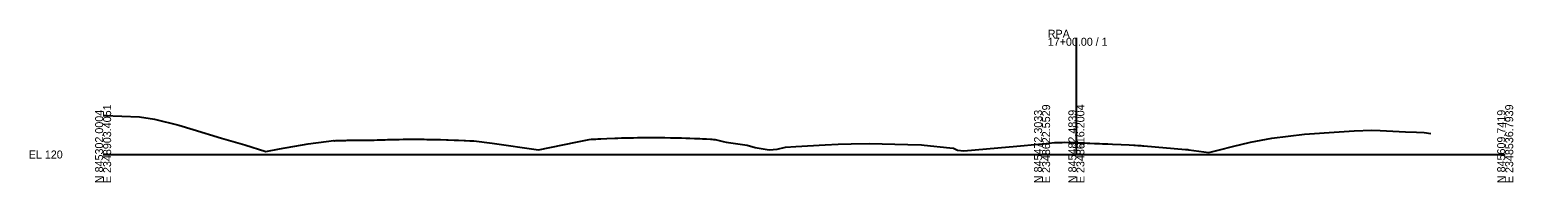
# Model space of a CAD drawing. Extents: x -76 to 2348158, y -10 to 845166.
# Drawn here: x 1224 to 1743, y 6490 to 6544 of the extents above; entities that cross this region are included whole.
import ezdxf

# ---------------------------------------------------------------- set-up
doc = ezdxf.new("R2010")
doc.units = 0
for name, color, linetype in [('Default', 7, 'Continuous'), ('Exist Cross Section Cell', 7, 'Continuous'), ('Exist XS Center Line Elevation Label', 7, 'Continuous'), ('Exist XS Ground Line', 7, 'Continuous')]:
    doc.layers.add(name, color=color, linetype=linetype)

msp = doc.modelspace()

# ---------------------------------------------------------------- linework, layer by layer
at = {"layer": 'Exist Cross Section Cell'}
for p, q in [((1590.45, 6500), (1590.45, 6540.75)), ((1250, 6500), (1578.45, 6500)), ((1578.45, 6500), (1590.45, 6500)), ((1590.45, 6500), (1740.45, 6500))]:
    msp.add_line(p, q, dxfattribs=at)
at = {"layer": 'Exist XS Ground Line'}
msp.add_lwpolyline([(1250, 6513.58), (1250.39, 6513.58), (1262.72, 6513.16), (1268.03, 6512.29), (1276.44, 6510.25), (1281.47, 6508.78), (1291.42, 6505.7), (1299.52, 6503.41), (1306.91, 6501.04), (1311.74, 6501.96), (1321.68, 6503.77), (1327.97, 6504.52), (1330.69, 6504.87), (1330.99, 6504.79), (1331.43, 6504.84), (1332.53, 6504.89), (1333.56, 6504.92), (1334.15, 6504.93), (1334.89, 6504.94), (1335.42, 6504.95), (1336.83, 6504.98), (1338.65, 6505), (1339.13, 6505), (1340.47, 6505.01), (1341.28, 6505.02), (1344.19, 6505.05), (1344.83, 6505.06), (1345.84, 6505.08), (1347.12, 6505.12), (1348.68, 6505.16), (1349.5, 6505.18), (1350.01, 6505.2), (1351.36, 6505.24), (1352.95, 6505.27), (1353.6, 6505.28), (1354.99, 6505.3), (1355.85, 6505.32), (1356.7, 6505.32), (1357.63, 6505.34), (1358.42, 6505.34), (1358.75, 6505.34), (1360.42, 6505.32), (1361.67, 6505.31), (1362.25, 6505.3), (1363.23, 6505.29), (1364.11, 6505.28), (1364.63, 6505.26), (1366.87, 6505.21), (1367.98, 6505.18), (1370.07, 6505.13), (1370.73, 6505.1), (1372.8, 6505.04), (1373.38, 6505.02), (1374.28, 6504.99), (1376.32, 6504.92), (1376.8, 6504.9), (1378.3, 6504.79), (1379.64, 6504.77), (1379.67, 6504.8), (1386.13, 6503.92), (1402.32, 6501.66), (1415.32, 6504.29), (1420.06, 6505.27), (1420.69, 6505.3), (1421.49, 6505.35), (1422.32, 6505.39), (1423.09, 6505.43), (1424.14, 6505.48), (1426.23, 6505.57), (1428.97, 6505.68), (1430.08, 6505.73), (1431.28, 6505.77), (1431.88, 6505.78), (1433.26, 6505.81), (1435.06, 6505.86), (1435.5, 6505.87), (1436.91, 6505.9), (1437.74, 6505.91), (1440.3, 6505.95), (1440.67, 6505.96), (1441.96, 6505.97), (1443.04, 6505.95), (1443.53, 6505.95), (1444.15, 6505.94), (1445.13, 6505.92), (1445.99, 6505.9), (1446.53, 6505.89), (1448.48, 6505.85), (1449.36, 6505.83), (1449.96, 6505.82), (1452.31, 6505.77), (1453.86, 6505.74), (1454.43, 6505.72), (1455.19, 6505.68), (1456.89, 6505.62), (1458.15, 6505.56), (1458.71, 6505.54), (1459.67, 6505.49), (1460.53, 6505.45), (1461.04, 6505.43), (1462.44, 6505.35), (1462.97, 6505.32), (1463.48, 6505.26), (1464.08, 6505.28), (1466.86, 6504.54), (1467.97, 6504.28), (1475.25, 6503.26), (1478.14, 6502.49), (1483.01, 6501.6), (1485.77, 6501.88), (1488.64, 6502.59), (1492.35, 6502.78), (1502.56, 6503.39), (1507.07, 6503.63), (1511.71, 6503.69), (1517.92, 6503.81), (1531.51, 6503.5), (1536.32, 6503.41), (1537.21, 6503.3), (1546.23, 6502.29), (1547.47, 6502.16), (1548.84, 6501.57), (1551.11, 6501.23), (1566.99, 6502.67), (1568.37, 6502.78), (1578.45, 6503.72), (1578.88, 6503.76), (1582.84, 6504.15), (1583.57, 6504.17), (1584.3, 6504.18), (1585.43, 6504.22), (1586.13, 6504.26), (1587.62, 6504.23), (1588.33, 6504.21), (1590.07, 6504.15), (1590.45, 6504.13), (1591.27, 6504.1), (1592, 6504.08), (1593.34, 6504.03), (1594.23, 6503.99), (1595.21, 6503.95), (1596.75, 6503.88), (1597.21, 6503.86), (1598.56, 6503.79), (1599.56, 6503.75), (1600.1, 6503.73), (1601.41, 6503.67), (1603.05, 6503.6), (1606.08, 6503.47), (1608.95, 6503.33), (1610.52, 6503.26), (1610.97, 6503.24), (1611.89, 6503.19), (1612.68, 6503.14), (1613.05, 6503.11), (1613.59, 6503.08), (1614.06, 6503.06), (1628.63, 6501.77), (1629.41, 6501.71), (1629.78, 6501.66), (1636.74, 6500.74), (1640.5, 6501.58), (1645.09, 6502.74), (1651.37, 6504.3), (1658.76, 6505.66), (1670.24, 6507.05), (1682.36, 6507.94), (1687.66, 6508.28), (1693.83, 6508.49), (1696.67, 6508.41), (1705.62, 6507.9), (1709.44, 6507.78), (1712.15, 6507.7), (1714.4, 6507.35)], dxfattribs=at)

# ---------------------------------------------------------------- texts
at = {"layer": 'Default'}
msp.add_text('-', height=0.0001, dxfattribs=at).set_placement((1250, 6500))
at = {"layer": 'Exist Cross Section Cell'}
for s, p in [('17+00.00 / 1', (1580.45, 6537.95)), ('RPA', (1580.45, 6540.75)), ('EL 120', (1224, 6498.6))]:
    msp.add_text(s, height=2.8, dxfattribs=at).set_placement(p)
for s, p in [('N 845302.0004', (1250, 6490)), ('E 2348903.4051', (1252.8, 6490)), ('N 845472.3033', (1578.45, 6490)), ('E 2348622.5529', (1581.25, 6490)), ('N 845482.4839', (1590.45, 6490)), ('E 2348616.2004', (1593.25, 6490)), ('N 845609.7419', (1740.45, 6490)), ('E 2348536.7939', (1743.25, 6490))]:
    msp.add_text(s, height=2.8, rotation=90, dxfattribs=at).set_placement(p)
at = {"layer": 'Exist XS Center Line Elevation Label'}
msp.add_text('124.13', height=1.2, dxfattribs=at).set_placement((1588.35, 6502.53))

doc.saveas('drawing.dxf')
